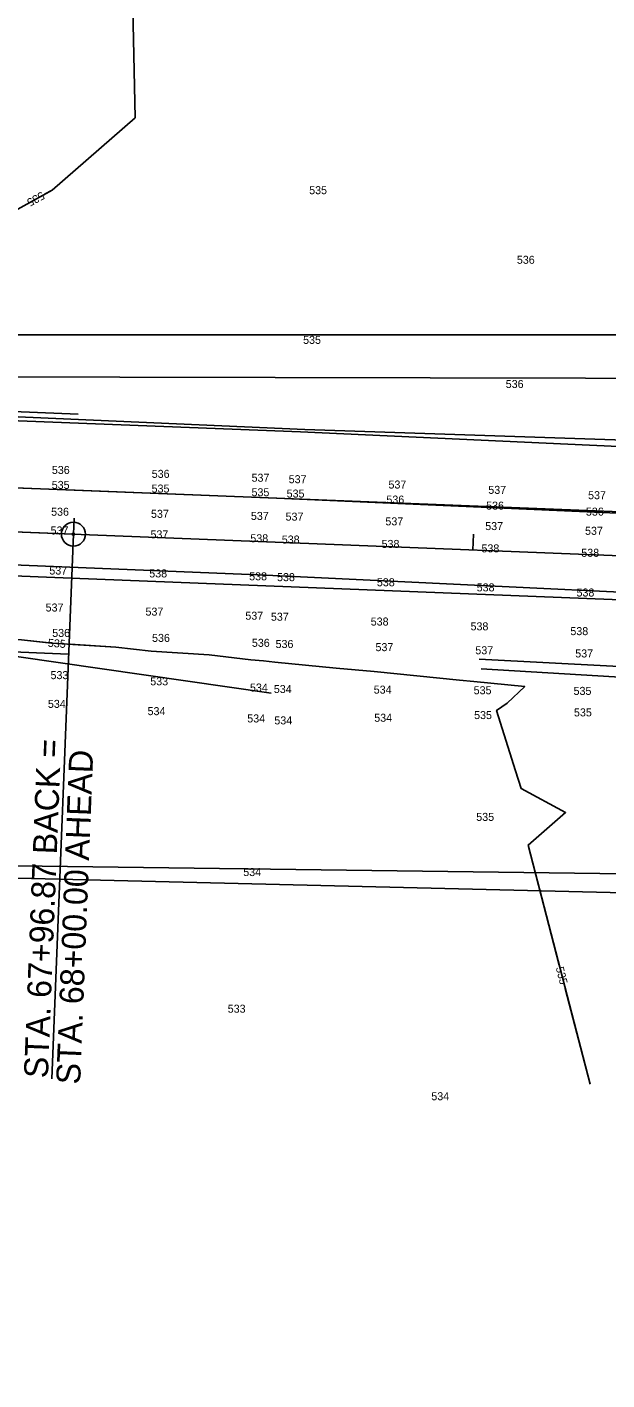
# Model space of a CAD drawing. Extents: x 1787461 to 1970323, y 938412 to 1118748.
# Drawn here: x 1968466.8 to 1968611.9, y 1117714.7 to 1118052.7 of the extents above; entities that cross this region are included whole.
import ezdxf

# ---------------------------------------------------------------- set-up
doc = ezdxf.new("R2010")
doc.units = 0
for name, color, linetype in [('Default', 7, 'Continuous'), ('HHA ADDITIONAL XSs', 7, 'Continuous'), ('Level 1', 7, 'Continuous'), ('RD_EX_DV_Prop', 7, 'Continuous'), ('RD_EX_Fence_Other', 7, 'Continuous'), ('RD_EX_Road', 7, 'Continuous'), ('RD_EX_VEG', 7, 'Continuous'), ('RD_HC_CL', 7, 'Continuous'), ('RD_HC_CL_Rel', 7, 'Continuous'), ('RD_HC_Data_Rel', 7, 'Continuous'), ('RD_HC_Data_Tic', 7, 'Continuous'), ('RD_HC_Data_Tic_Rel', 7, 'Continuous'), ('RD_PD_Final_TrvlWay', 7, 'Continuous')]:
    doc.layers.add(name, color=color, linetype=linetype)

msp = doc.modelspace()

# ---------------------------------------------------------------- linework, layer by layer
at = {"layer": 'Default'}
for points in [[(1968476.98, 1118199.36), (1968477.02, 1118190.46), (1968480.85, 1118156.66), (1968481.33, 1118149.27), (1968481.37, 1118148.66), (1968481.28, 1118145.33), (1968482.16, 1118136.42), (1968493.04, 1118069.17), (1968493.9, 1118030.09), (1968473.08, 1118012.02), (1968471.33, 1118011.05)], [(1968476.98, 1118199.36), (1968477.02, 1118190.46), (1968480.85, 1118156.66), (1968481.33, 1118149.27), (1968481.37, 1118148.66), (1968481.28, 1118145.33), (1968482.16, 1118136.42), (1968493.04, 1118069.17), (1968493.9, 1118030.09), (1968473.08, 1118012.02), (1968471.33, 1118011.05)], [(1968476.98, 1118199.36), (1968477.02, 1118190.46), (1968480.85, 1118156.66), (1968481.33, 1118149.27), (1968481.37, 1118148.66), (1968481.28, 1118145.33), (1968482.16, 1118136.42), (1968493.04, 1118069.17), (1968493.9, 1118030.09), (1968473.08, 1118012.02), (1968471.33, 1118011.05)], [(1968476.98, 1118199.36), (1968477.02, 1118190.46), (1968480.85, 1118156.66), (1968481.33, 1118149.27), (1968481.37, 1118148.66), (1968481.28, 1118145.33), (1968482.16, 1118136.42), (1968493.04, 1118069.17), (1968493.9, 1118030.09), (1968473.08, 1118012.02), (1968471.33, 1118011.05)], [(1968476.98, 1118199.36), (1968477.02, 1118190.46), (1968480.85, 1118156.66), (1968481.33, 1118149.27), (1968481.37, 1118148.66), (1968481.28, 1118145.33), (1968482.16, 1118136.42), (1968493.04, 1118069.17), (1968493.9, 1118030.09), (1968473.08, 1118012.02), (1968471.33, 1118011.05)], [(1968476.98, 1118199.36), (1968477.02, 1118190.46), (1968480.85, 1118156.66), (1968481.33, 1118149.27), (1968481.37, 1118148.66), (1968481.28, 1118145.33), (1968482.16, 1118136.42), (1968493.04, 1118069.17), (1968493.9, 1118030.09), (1968473.08, 1118012.02), (1968471.33, 1118011.05)], [(1968493.04, 1118069.17), (1968493.9, 1118030.09), (1968473.08, 1118012.02), (1968437.02, 1117992.09)], [(1968274.29, 1117907.26), (1968285.56, 1117906.97), (1968289.06, 1117906.79), (1968310.55, 1117906.23), (1968318.92, 1117906.01), (1968320.39, 1117905.94), (1968341.69, 1117905.21), (1968345.39, 1117905.16), (1968366.3, 1117904.45), (1968370.37, 1117906.03), (1968391.31, 1117905.47), (1968390.95, 1117903.71), (1968395.45, 1117903.52), (1968415.22, 1117902.85), (1968420.46, 1117902.62), (1968422.69, 1117902.54), (1968423.09, 1117902.52), (1968441.69, 1117901.38), (1968448.04, 1117900.73), (1968465.44, 1117899.64), (1968471.63, 1117898.97)], [(1968274.29, 1117907.26), (1968285.56, 1117906.97), (1968289.06, 1117906.79), (1968310.55, 1117906.23), (1968318.92, 1117906.01), (1968320.39, 1117905.94), (1968341.69, 1117905.21), (1968345.39, 1117905.16), (1968366.3, 1117904.45), (1968370.37, 1117906.03), (1968391.31, 1117905.47), (1968390.95, 1117903.71), (1968395.45, 1117903.52), (1968415.22, 1117902.85), (1968420.46, 1117902.62), (1968422.69, 1117902.54), (1968423.09, 1117902.52), (1968441.69, 1117901.38), (1968448.04, 1117900.73), (1968465.44, 1117899.64), (1968471.63, 1117898.97)], [(1968274.29, 1117907.26), (1968285.56, 1117906.97), (1968289.06, 1117906.79), (1968310.55, 1117906.23), (1968318.92, 1117906.01), (1968320.39, 1117905.94), (1968341.69, 1117905.21), (1968345.39, 1117905.16), (1968366.3, 1117904.45), (1968370.37, 1117906.03), (1968391.31, 1117905.47), (1968390.95, 1117903.71), (1968395.45, 1117903.52), (1968415.22, 1117902.85), (1968420.46, 1117902.62), (1968422.69, 1117902.54), (1968423.09, 1117902.52), (1968441.69, 1117901.38), (1968448.04, 1117900.73), (1968465.44, 1117899.64), (1968471.63, 1117898.97)], [(1968274.29, 1117907.26), (1968285.56, 1117906.97), (1968289.06, 1117906.79), (1968310.55, 1117906.23), (1968318.92, 1117906.01), (1968320.39, 1117905.94), (1968341.69, 1117905.21), (1968345.39, 1117905.16), (1968366.3, 1117904.45), (1968370.37, 1117906.03), (1968391.31, 1117905.47), (1968390.95, 1117903.71), (1968395.45, 1117903.52), (1968415.22, 1117902.85), (1968420.46, 1117902.62), (1968422.69, 1117902.54), (1968423.09, 1117902.52), (1968441.69, 1117901.38), (1968448.04, 1117900.73), (1968465.44, 1117899.64), (1968471.63, 1117898.97)], [(1968274.29, 1117907.26), (1968285.56, 1117906.97), (1968289.06, 1117906.79), (1968310.55, 1117906.23), (1968318.92, 1117906.01), (1968320.39, 1117905.94), (1968341.69, 1117905.21), (1968345.39, 1117905.16), (1968366.3, 1117904.45), (1968370.37, 1117906.03), (1968391.31, 1117905.47), (1968390.95, 1117903.71), (1968395.45, 1117903.52), (1968415.22, 1117902.85), (1968420.46, 1117902.62), (1968422.69, 1117902.54), (1968423.09, 1117902.52), (1968441.69, 1117901.38), (1968448.04, 1117900.73), (1968465.44, 1117899.64), (1968471.63, 1117898.97)], [(1968274.29, 1117907.26), (1968285.56, 1117906.97), (1968289.06, 1117906.79), (1968310.55, 1117906.23), (1968318.92, 1117906.01), (1968320.39, 1117905.94), (1968341.69, 1117905.21), (1968345.39, 1117905.16), (1968366.3, 1117904.45), (1968370.37, 1117906.03), (1968391.31, 1117905.47), (1968390.95, 1117903.71), (1968395.45, 1117903.52), (1968415.22, 1117902.85), (1968420.46, 1117902.62), (1968422.69, 1117902.54), (1968423.09, 1117902.52), (1968441.69, 1117901.38), (1968448.04, 1117900.73), (1968465.44, 1117899.64), (1968471.63, 1117898.97)], [(1968465.44, 1117899.64), (1968472.98, 1117898.83), (1968489.02, 1117897.8), (1968497.91, 1117896.8), (1968512.39, 1117895.85), (1968522.84, 1117894.62), (1968525.94, 1117894.41), (1968528.78, 1117894.07), (1968544.12, 1117892.57), (1968553.69, 1117891.7), (1968575.02, 1117889.58), (1968578.59, 1117889.25), (1968591.33, 1117887.96), (1968586.88, 1117883.84), (1968584.26, 1117881.99), (1968589.03, 1117866.91), (1968590.43, 1117862.49), (1968601.54, 1117856.54), (1968592.13, 1117848.34), (1968607.64, 1117788.59)], [(1968477.61, 1117898.53), (1968489.02, 1117897.8), (1968497.91, 1117896.8), (1968512.39, 1117895.85), (1968522.84, 1117894.62), (1968525.94, 1117894.41), (1968528.78, 1117894.07), (1968544.12, 1117892.57), (1968553.69, 1117891.7), (1968575.02, 1117889.58), (1968578.59, 1117889.25), (1968591.33, 1117887.96), (1968586.88, 1117883.84), (1968584.26, 1117881.99), (1968589.03, 1117866.91), (1968590.43, 1117862.49), (1968601.54, 1117856.54), (1968592.13, 1117848.34), (1968599.91, 1117818.36)], [(1968477.61, 1117898.53), (1968489.02, 1117897.8), (1968497.91, 1117896.8), (1968512.39, 1117895.85), (1968522.84, 1117894.62), (1968525.94, 1117894.41), (1968528.78, 1117894.07), (1968544.12, 1117892.57), (1968553.69, 1117891.7), (1968575.02, 1117889.58), (1968578.59, 1117889.25), (1968591.33, 1117887.96), (1968586.88, 1117883.84), (1968584.26, 1117881.99), (1968589.03, 1117866.91), (1968590.43, 1117862.49), (1968601.54, 1117856.54), (1968592.13, 1117848.34), (1968599.91, 1117818.36)], [(1968477.61, 1117898.53), (1968489.02, 1117897.8), (1968497.91, 1117896.8), (1968512.39, 1117895.85), (1968522.84, 1117894.62), (1968525.94, 1117894.41), (1968528.78, 1117894.07), (1968544.12, 1117892.57), (1968553.69, 1117891.7), (1968575.02, 1117889.58), (1968578.59, 1117889.25), (1968591.33, 1117887.96), (1968586.88, 1117883.84), (1968584.26, 1117881.99), (1968589.03, 1117866.91), (1968590.43, 1117862.49), (1968601.54, 1117856.54), (1968592.13, 1117848.34), (1968599.91, 1117818.36)], [(1968477.61, 1117898.53), (1968489.02, 1117897.8), (1968497.91, 1117896.8), (1968512.39, 1117895.85), (1968522.84, 1117894.62), (1968525.94, 1117894.41), (1968528.78, 1117894.07), (1968544.12, 1117892.57), (1968553.69, 1117891.7), (1968575.02, 1117889.58), (1968578.59, 1117889.25), (1968591.33, 1117887.96), (1968586.88, 1117883.84), (1968584.26, 1117881.99), (1968589.03, 1117866.91), (1968590.43, 1117862.49), (1968601.54, 1117856.54), (1968592.13, 1117848.34), (1968599.91, 1117818.36)], [(1968477.61, 1117898.53), (1968489.02, 1117897.8), (1968497.91, 1117896.8), (1968512.39, 1117895.85), (1968522.84, 1117894.62), (1968525.94, 1117894.41), (1968528.78, 1117894.07), (1968544.12, 1117892.57), (1968553.69, 1117891.7), (1968575.02, 1117889.58), (1968578.59, 1117889.25), (1968591.33, 1117887.96), (1968586.88, 1117883.84), (1968584.26, 1117881.99), (1968589.03, 1117866.91), (1968590.43, 1117862.49), (1968601.54, 1117856.54), (1968592.13, 1117848.34), (1968599.91, 1117818.36)], [(1968477.61, 1117898.53), (1968489.02, 1117897.8), (1968497.91, 1117896.8), (1968512.39, 1117895.85), (1968522.84, 1117894.62), (1968525.94, 1117894.41), (1968528.78, 1117894.07), (1968544.12, 1117892.57), (1968553.69, 1117891.7), (1968575.02, 1117889.58), (1968578.59, 1117889.25), (1968591.33, 1117887.96), (1968586.88, 1117883.84), (1968584.26, 1117881.99), (1968589.03, 1117866.91), (1968590.43, 1117862.49), (1968601.54, 1117856.54), (1968592.13, 1117848.34), (1968599.91, 1117818.36)], [(1968601.42, 1117812.55), (1968607.64, 1117788.59)], [(1968601.42, 1117812.55), (1968607.64, 1117788.59)], [(1968601.42, 1117812.55), (1968607.64, 1117788.59)], [(1968601.42, 1117812.55), (1968607.64, 1117788.59)], [(1968601.42, 1117812.55), (1968607.64, 1117788.59)], [(1968601.42, 1117812.55), (1968607.64, 1117788.59)]]:
    msp.add_lwpolyline(points, dxfattribs=at)
at = {"layer": 'HHA ADDITIONAL XSs'}
for p, q in [((1968297.47, 1117963.25), (1968479.61, 1117956.02)), ((1968295.09, 1117903.29), (1968477.23, 1117896.06))]:
    msp.add_line(p, q, dxfattribs=at)
for points in [[(1969266.55, 1117963.61), (1967907.56, 1117966.55), (1967403.98, 1117771.66), (1967075.57, 1117641.84)], [(1969308.89, 1117819.66), (1967912.94, 1117853.44), (1967442.55, 1117653.93), (1967107.32, 1117508.48)]]:
    msp.add_lwpolyline(points, dxfattribs=at)
at = {"layer": 'Level 1'}
for points in [[(1968647.29, 1117975.82), (1967967.92, 1117975.82), (1967727.47, 1117916.63), (1966985.13, 1117603.01)], [(1968654.57, 1117840.68), (1968058.24, 1117848.48), (1967686.38, 1117740.3), (1966964.76, 1117453.35)]]:
    msp.add_lwpolyline(points, dxfattribs=at)
at = {"layer": 'RD_EX_DV_Prop'}
msp.add_line((1968370.12, 1117930.34), (1969277.79, 1117894.3), dxfattribs=at)
at = {"layer": 'RD_EX_Fence_Other'}
for points in [[(1967944.7, 1118004.73), (1967946.48, 1117961.88), (1967965.46, 1117964.9), (1968008.75, 1117969.86), (1968061.54, 1117969.15), (1968104.37, 1117971.22), (1968157.32, 1117967.69), (1968212.92, 1117965.31), (1968421.1, 1117957.24), (1968536.3, 1117952.23)], [(1968536.3, 1117952.23), (1968681.42, 1117947.34), (1968783.46, 1117943.44), (1968890.68, 1117939.26), (1968990.9, 1117933.42), (1969093.99, 1117930.77), (1969190.99, 1117925.01), (1969281.24, 1117923.59)], [(1968579.94, 1117894.82), (1968678.66, 1117889.64), (1968779.4, 1117886.8), (1968885.65, 1117881.12), (1968982.76, 1117877.17), (1969084.96, 1117872.96), (1969186.26, 1117869.55), (1969289.22, 1117863.98)]]:
    msp.add_lwpolyline(points, dxfattribs=at)
at = {"layer": 'RD_EX_Road'}
for points in [[(1968157.47, 1117947.92), (1968210.83, 1117946.57), (1968317.56, 1117942.64), (1968421.53, 1117939.29), (1968529.31, 1117935.06)], [(1968529.31, 1117935.06), (1968680.74, 1117928.37), (1968782, 1117924.72), (1968887.41, 1117920.79), (1968989.99, 1117916.45), (1969090.76, 1117912.42), (1969189.86, 1117908.01), (1969282.04, 1117904.78)], [(1968157.93, 1117928.73), (1968211.27, 1117927.33), (1968316.32, 1117923.79), (1968420.29, 1117920.11), (1968526.59, 1117915.77)], [(1968526.59, 1117915.77), (1968679.57, 1117908.43), (1968780.48, 1117904.73), (1968886.63, 1117901.2), (1968987.42, 1117897.59), (1969088.87, 1117892.19), (1969188.08, 1117888.4), (1969281.71, 1117884.78)]]:
    msp.add_lwpolyline(points, dxfattribs=at)
at = {"layer": 'RD_EX_VEG'}
for points in [[(1967420.8, 1117819.08), (1967452.15, 1117758.28), (1967558.57, 1117805.53), (1967843.24, 1117926.43), (1967916.63, 1117956.61), (1968008.44, 1117968.2), (1968060.25, 1117967.44), (1968104.58, 1117972.69), (1968157.63, 1117966.15), (1968211.15, 1117963.44), (1968421.93, 1117955.99), (1968535.19, 1117951.62)], [(1968535.19, 1117951.62), (1968681.64, 1117944.89), (1968783.26, 1117941.54), (1968890.11, 1117938.32), (1968991.04, 1117932.18), (1969094.36, 1117929.93), (1969190.81, 1117923.37), (1969281.69, 1117922.69)], [(1967302.31, 1117610.37), (1967337.76, 1117649.58), (1967352.05, 1117663.92), (1967393.53, 1117676.59), (1967483.38, 1117717.02), (1967710.35, 1117806.03), (1967888.86, 1117873.57), (1967928.06, 1117882.04), (1967957.92, 1117887.35), (1967975.7, 1117893.86), (1968013.09, 1117903.71), (1968102.91, 1117899.22), (1968154.08, 1117904.84), (1968208.62, 1117905.24), (1968319.32, 1117902.87), (1968421.81, 1117901.58), (1968527.92, 1117886.31)], [(1968580.4, 1117892.39), (1968677.7, 1117886.58), (1968780.39, 1117884.76), (1968885.66, 1117879.53), (1968982.9, 1117878.1), (1969085.82, 1117874.51), (1969187.45, 1117870.95), (1969289.3, 1117866.04)]]:
    msp.add_lwpolyline(points, dxfattribs=at)
at = {"layer": 'RD_HC_CL'}
msp.add_line((1968119.1, 1117940.3), (1969277.79, 1117894.3), dxfattribs=at)
at = {"layer": 'RD_HC_CL_Rel'}
msp.add_line((1968296.28, 1117933.27), (1968478.42, 1117926.04), dxfattribs=at)
at = {"layer": 'RD_HC_Data_Rel'}
msp.add_line((1968478.42, 1117926.04), (1968473.02, 1117789.99), dxfattribs=at)
for radius in [3, 0.282]:
    msp.add_circle((1968478.42, 1117926.04), radius, dxfattribs=at)
at = {"layer": 'RD_HC_Data_Tic'}
for p, q in [((1968478.42, 1117926.04), (1968478.58, 1117930.04)), ((1968578.34, 1117922.07), (1968578.5, 1117926.07))]:
    msp.add_line(p, q, dxfattribs=at)
at = {"layer": 'RD_HC_Data_Tic_Rel'}
msp.add_line((1968478.42, 1117926.04), (1968478.58, 1117930.04), dxfattribs=at)
at = {"layer": 'RD_PD_Final_TrvlWay'}
for p, q in [((1968296.72, 1117944.26), (1968478.85, 1117937.03)), ((1968478.85, 1117937.03), (1969278.22, 1117905.3)), ((1968295.84, 1117922.28), (1968477.98, 1117915.05)), ((1968477.98, 1117915.05), (1969277.35, 1117883.31))]:
    msp.add_line(p, q, dxfattribs=at)

# ---------------------------------------------------------------- texts
at = {"layer": 'Default'}
for rotation, p in [(208.9298, (1968470.48, 1118011.72)), (208.9298, (1968470.48, 1118011.72)), (208.9298, (1968470.48, 1118011.72)), (208.9298, (1968470.48, 1118011.72)), (208.9298, (1968470.48, 1118011.72)), (208.9298, (1968470.48, 1118011.72)), (355.7822, (1968471.98, 1117897.92)), (355.7822, (1968471.98, 1117897.92)), (355.7822, (1968471.98, 1117897.92)), (355.7822, (1968471.98, 1117897.92)), (355.7822, (1968471.98, 1117897.92)), (355.7822, (1968471.98, 1117897.92)), (284.5554, (1968599.05, 1117817.69)), (284.5554, (1968599.05, 1117817.69)), (284.5554, (1968599.05, 1117817.69)), (284.5554, (1968599.05, 1117817.69)), (284.5554, (1968599.05, 1117817.69)), (284.5554, (1968599.05, 1117817.69))]:
    msp.add_text('535', height=2, rotation=rotation, dxfattribs=at).set_placement(p)
for s, p in [('535', (1968537.39, 1118010.98)), ('536', (1968589.34, 1117993.59)), ('535', (1968535.88, 1117973.58)), ('536', (1968586.56, 1117962.56)), ('536', (1968473.03, 1117941.08)), ('536', (1968498.01, 1117940.11)), ('537', (1968522.98, 1117939.14)), ('537', (1968532.27, 1117938.77)), ('535', (1968473, 1117937.35)), ('535', (1968497.98, 1117936.43)), ('535', (1968522.97, 1117935.51)), ('535', (1968531.76, 1117935.18)), ('537', (1968557.23, 1117937.44)), ('537', (1968582.2, 1117936.11)), ('536', (1968556.71, 1117933.68)), ('536', (1968581.66, 1117932.17)), ('537', (1968607.16, 1117934.78)), ('536', (1968472.84, 1117930.64)), ('537', (1968497.83, 1117930.12)), ('537', (1968522.82, 1117929.6)), ('537', (1968531.49, 1117929.42)), ('537', (1968556.46, 1117928.24)), ('536', (1968606.62, 1117930.67)), ('537', (1968472.72, 1117925.97)), ('537', (1968497.7, 1117924.99)), ('537', (1968581.43, 1117927.06)), ('537', (1968606.4, 1117925.88)), ('538', (1968522.68, 1117924.01)), ('538', (1968530.54, 1117923.7)), ('538', (1968555.51, 1117922.6)), ('538', (1968580.49, 1117921.49)), ('538', (1968605.46, 1117920.39)), ('537', (1968472.4, 1117915.95)), ('538', (1968497.39, 1117915.23)), ('538', (1968522.38, 1117914.51)), ('538', (1968529.36, 1117914.3)), ('538', (1968554.33, 1117913.02)), ('538', (1968579.3, 1117911.74)), ('538', (1968604.26, 1117910.46)), ('537', (1968471.47, 1117906.71)), ('537', (1968496.45, 1117905.69)), ('537', (1968521.43, 1117904.67)), ('537', (1968527.82, 1117904.41)), ('538', (1968552.79, 1117903.21)), ('538', (1968577.76, 1117902.01)), ('536', (1968473.12, 1117900.36)), ('536', (1968498.09, 1117899.12)), ('536', (1968523.06, 1117897.89)), ('538', (1968602.73, 1117900.81)), ('536', (1968528.99, 1117897.6)), ('537', (1968553.98, 1117896.81)), ('537', (1968578.96, 1117896.03)), ('537', (1968603.95, 1117895.24)), ('533', (1968472.69, 1117889.82)), ('533', (1968497.64, 1117888.27)), ('534', (1968522.59, 1117886.72)), ('534', (1968528.55, 1117886.35)), ('534', (1968553.54, 1117886.2)), ('535', (1968578.54, 1117886.04)), ('535', (1968603.53, 1117885.88)), ('534', (1968472.04, 1117882.64)), ('534', (1968496.97, 1117880.82)), ('534', (1968521.91, 1117879)), ('534', (1968528.68, 1117878.51)), ('534', (1968553.67, 1117879.17)), ('535', (1968578.65, 1117879.84)), ('535', (1968603.63, 1117880.51)), ('535', (1968579.19, 1117854.4)), ('534', (1968520.9, 1117840.62)), ('533', (1968517.02, 1117806.48)), ('534', (1968567.95, 1117784.61))]:
    msp.add_text(s, height=2, dxfattribs=at).set_placement(p)
at = {"layer": 'RD_HC_Data_Rel'}
for s, p in [('STA. 67+96.87 BACK = ', (1968472.03, 1117790.05)), ('STA. 68+00.00 AHEAD', (1968480.09, 1117788.48))]:
    msp.add_text(s, height=6, rotation=87.7266, dxfattribs=at).set_placement(p)

doc.saveas('drawing.dxf')
